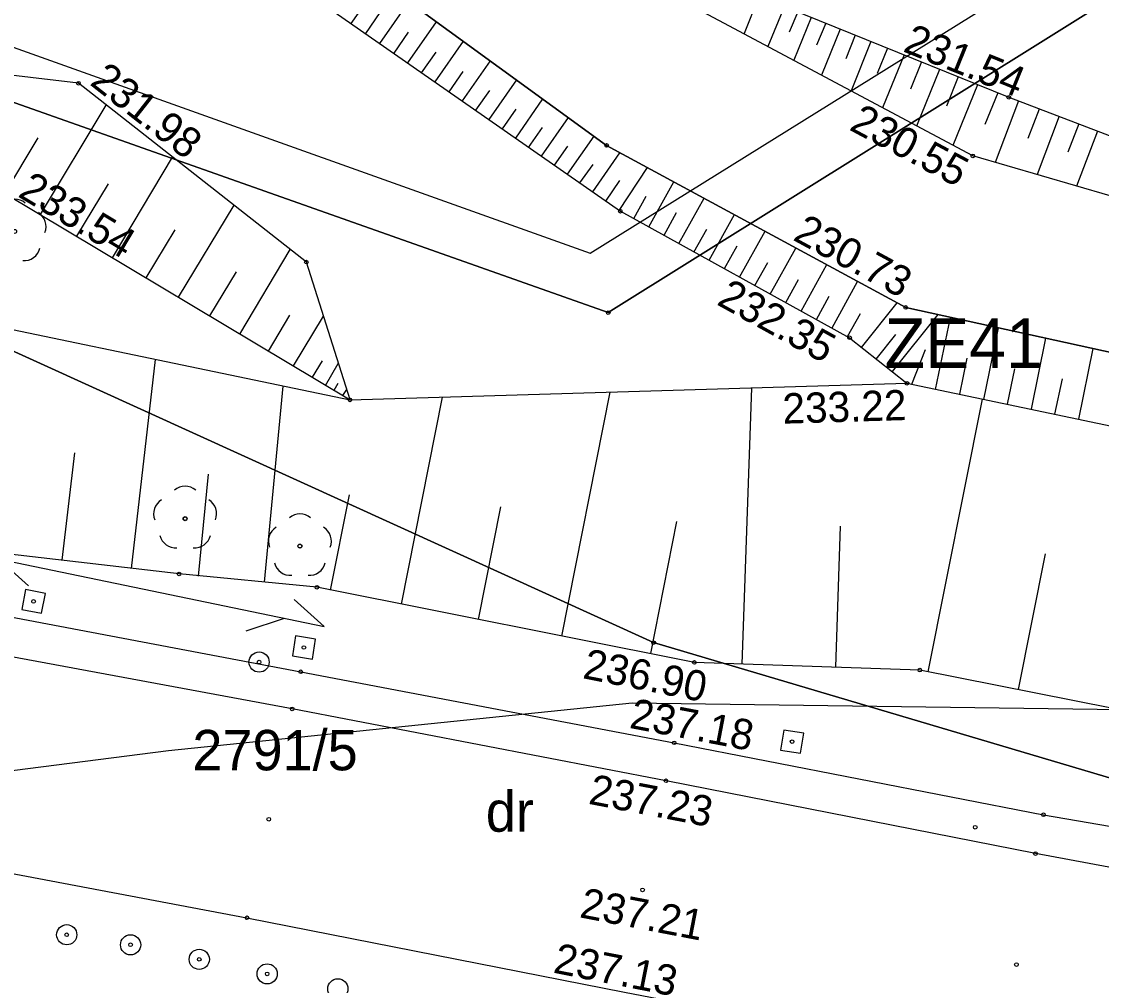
# Model space of a CAD drawing. Extents: x 6596400 to 6597200, y 5539751 to 5540251.
# Drawn here: x 6596761.51 to 6596788.23, y 5540079.28 to 5540103.13 of the extents above; entities that cross this region are included whole.
import ezdxf

# ---------------------------------------------------------------- set-up
doc = ezdxf.new("R2010")
doc.units = 0
for name, color, linetype in [('000 Inne (niezydentyfikowane)', 7, 'Continuous'), ('140-Punkty robocze', 7, 'Continuous'), ('203-punkt graniczny', 7, 'Continuous'), ('210-oznaczenie konturu użytku gruntowego', 7, 'Continuous'), ('211-numer działki ewidencyjnej', 7, 'Continuous'), ('217-kontur klasyfikacyjny', 7, 'Continuous'), ('218-kontur użytku gruntowego', 7, 'Continuous'), ('219-działka ewidencyjna', 7, 'Continuous'), ('bariera ochronna', 7, 'Continuous'), ('drzewo liściaste', 7, 'Continuous'), ('jezdnia', 7, 'Continuous'), ('Linia obszaru zagospodarowania terenu', 7, 'Continuous'), ('Opis obszaru zagospodarowania terenu', 7, 'Continuous'), ('pikieta sztuczna', 7, 'Continuous'), ('pikieta sztuczna-Atr2', 7, 'Continuous'), ('przewód telekomunikacyjny napowietrzny', 7, 'Continuous'), ('skarpa nieumocniona', 7, 'Continuous'), ('skarpa umocniona', 7, 'Continuous'), ('woda płynąca', 7, 'Continuous'), ('właz do komory lub kanału - kwadratowy', 7, 'Continuous'), ('właz do komory lub kanału - okrągły', 7, 'Continuous')]:
    doc.layers.add(name, color=color, linetype=linetype)

# ---------------------------------------------------------------- blocks, each defined once
blk = doc.blocks.new('203')
blk.add_circle((0, 0), 0.045)
blk = doc.blocks.new('SUTP')
for p, q in [((0, 0), (0.866, 0.5)), ((9.232, 0), (8.366, 0.5)), ((0, 0), (9.232, 0)), ((1.866, -0.5), (1, 0)), ((7.366, -0.5), (8.232, 0))]:
    blk.add_line(p, q)
blk = doc.blocks.new('OP021')
blk.add_circle((0, 0), 0.05)
for centre, start, end in [((0, 0.4), 49.272, 130.728), ((-0.38, 0.124), 121.308, 202.548), ((0.38, 0.124), 337.452, 58.692), ((-0.235, -0.324), 193.221, 274.871), ((0.235, -0.324), 265.129, 346.779)]:
    blk.add_arc(centre, 0.4, start, end)
blk = doc.blocks.new('US22A')
blk.add_lwpolyline([(-0.25, -0.25), (0.25, -0.25), (0.25, 0.25), (-0.25, 0.25)], close=True)
blk = doc.blocks.new('US22')
blk.add_circle((0, 0), 0.25)
blk = doc.blocks.new('PIKIETA')
blk.add_circle((0, 0), 0.045)
blk = doc.blocks.new('PW01')
blk.add_circle((0, 0), 0.045)

msp = doc.modelspace()

# ---------------------------------------------------------------- linework, layer by layer
at = {"layer": '000 Inne (niezydentyfikowane)'}
for p, q in [((6596779.76, 5540103.77), (6596779.39, 5540102.84)), ((6596780.39, 5540103.52), (6596779.98, 5540102.52)), ((6596780.72, 5540103.38), (6596780.51, 5540102.87)), ((6596781.05, 5540103.24), (6596780.62, 5540102.18)), ((6596781.41, 5540103.1), (6596781.18, 5540102.55)), ((6596781.77, 5540102.95), (6596781.31, 5540101.81)), ((6596782.14, 5540102.8), (6596781.91, 5540102.21)), ((6596782.53, 5540102.64), (6596782.04, 5540101.42)), ((6596782.94, 5540102.48), (6596782.68, 5540101.85)), ((6596783.35, 5540102.31), (6596782.82, 5540101)), ((6596783.78, 5540102.14), (6596783.51, 5540101.46)), ((6596784.23, 5540101.95), (6596783.66, 5540100.55)), ((6596784.69, 5540101.77), (6596784.4, 5540101.04)), ((6596785.17, 5540101.57), (6596784.56, 5540100.07)), ((6596785.67, 5540101.37), (6596785.35, 5540100.59)), ((6596786.18, 5540101.17), (6596785.6, 5540099.65)), ((6596786.69, 5540100.97), (6596786.41, 5540100.24)), ((6596787.19, 5540100.79), (6596786.64, 5540099.35)), ((6596787.67, 5540100.6), (6596787.4, 5540099.9)), ((6596788.14, 5540100.42), (6596787.62, 5540099.06)), ((6596764.23, 5540089.6), (6596764.83, 5540094.77)), ((6596767.52, 5540089.26), (6596767.99, 5540094.11)), ((6596774.88, 5540087.92), (6596776.08, 5540093.96)), ((6596779.34, 5540087.23), (6596779.58, 5540094.07)), ((6596770.91, 5540088.71), (6596771.93, 5540093.84)), ((6596783.95, 5540087.04), (6596785.29, 5540093.79)), ((6596762.52, 5540089.8), (6596762.83, 5540092.46)), ((6596765.89, 5540089.41), (6596766.14, 5540091.93)), ((6596769.16, 5540089.06), (6596769.63, 5540091.42)), ((6596772.82, 5540088.33), (6596773.37, 5540091.12)), ((6596777.08, 5540087.49), (6596777.73, 5540090.76)), ((6596781.66, 5540087.15), (6596781.78, 5540090.64)), ((6596786.18, 5540086.6), (6596786.85, 5540089.96))]:
    msp.add_line(p, q, dxfattribs=at)
for points in [[(6596769.67, 5540103.09), (6596770.41, 5540104.14)], [(6596770.38, 5540102.59), (6596771.1, 5540103.63)], [(6596770.03, 5540102.84), (6596770.39, 5540103.36)], [(6596771.07, 5540102.11), (6596771.78, 5540103.13)], [(6596770.73, 5540102.35), (6596771.09, 5540102.87)], [(6596771.75, 5540101.64), (6596772.45, 5540102.65)], [(6596771.41, 5540101.87), (6596771.77, 5540102.38)], [(6596772.42, 5540101.17), (6596773.12, 5540102.16)], [(6596772.09, 5540101.4), (6596772.44, 5540101.9)], [(6596773.08, 5540100.71), (6596773.77, 5540101.69)], [(6596772.75, 5540100.94), (6596773.1, 5540101.43)], [(6596773.74, 5540100.25), (6596774.41, 5540101.22)], [(6596761.98, 5540098.36), (6596763.61, 5540101.07)], [(6596773.41, 5540100.48), (6596773.75, 5540100.97)], [(6596774.38, 5540099.8), (6596775.05, 5540100.76)], [(6596774.06, 5540100.02), (6596774.4, 5540100.51)], [(6596761.1, 5540098.88), (6596761.92, 5540100.26)], [(6596774.7, 5540099.58), (6596775.03, 5540100.05)], [(6596775.02, 5540099.36), (6596775.68, 5540100.3)], [(6596763.76, 5540097.29), (6596765.25, 5540099.78)], [(6596775.65, 5540098.92), (6596776.32, 5540099.89)], [(6596775.33, 5540099.14), (6596775.66, 5540099.6)], [(6596776.3, 5540098.46), (6596777, 5540099.52)], [(6596762.88, 5540097.82), (6596763.66, 5540099.12)], [(6596775.97, 5540098.69), (6596776.32, 5540099.2)], [(6596777.03, 5540098.05), (6596777.65, 5540099.17)], [(6596776.66, 5540098.26), (6596776.97, 5540098.81)], [(6596777.78, 5540097.64), (6596778.4, 5540098.76)], [(6596765.4, 5540096.31), (6596766.77, 5540098.59)], [(6596777.41, 5540097.85), (6596777.72, 5540098.41)], [(6596778.53, 5540097.23), (6596779.15, 5540098.36)], [(6596764.6, 5540096.79), (6596765.31, 5540097.98)], [(6596778.15, 5540097.43), (6596778.47, 5540098)], [(6596779.28, 5540096.81), (6596779.91, 5540097.95)], [(6596766.91, 5540095.4), (6596768.16, 5540097.49)], [(6596778.91, 5540097.02), (6596779.22, 5540097.58)], [(6596780.04, 5540096.39), (6596780.67, 5540097.53)], [(6596779.66, 5540096.6), (6596779.98, 5540097.17)], [(6596780.8, 5540095.97), (6596781.44, 5540097.12)], [(6596766.17, 5540095.85), (6596766.83, 5540096.94)], [(6596780.42, 5540096.18), (6596780.74, 5540096.75)], [(6596781.57, 5540095.55), (6596782.2, 5540096.7)], [(6596781.18, 5540095.76), (6596781.5, 5540096.34)], [(6596782.3, 5540095.07), (6596783.18, 5540096.17)], [(6596767.62, 5540094.98), (6596768.15, 5540095.87)], [(6596768.24, 5540094.61), (6596768.98, 5540095.84)], [(6596781.95, 5540095.34), (6596782.27, 5540095.91)], [(6596783.06, 5540094.47), (6596784.19, 5540095.88)], [(6596784.13, 5540094.03), (6596784.5, 5540095.81)], [(6596785.32, 5540093.78), (6596785.69, 5540095.55)], [(6596782.66, 5540094.78), (6596783.15, 5540095.39)], [(6596786.5, 5540093.54), (6596786.86, 5540095.3)], [(6596783.54, 5540094.16), (6596783.88, 5540095.02)], [(6596787.67, 5540093.29), (6596788.03, 5540095.04)], [(6596768.71, 5540094.33), (6596768.96, 5540094.74)], [(6596784.73, 5540093.91), (6596784.91, 5540094.8)], [(6596769.03, 5540094.13), (6596769.35, 5540094.67)], [(6596785.91, 5540093.66), (6596786.09, 5540094.54)], [(6596769.25, 5540094.01), (6596769.35, 5540094.18)], [(6596787.08, 5540093.42), (6596787.27, 5540094.29)], [(6596769.46, 5540093.88), (6596769.56, 5540094.03)]]:
    msp.add_lwpolyline(points, dxfattribs=at)
at = {"layer": '217-kontur klasyfikacyjny'}
for points in [[(6596791.43, 5540105.56), (6596776.03, 5540095.93)], [(6596776.03, 5540095.93), (6596757.93, 5540102.33)], [(6596758.2, 5540096.39), (6596777.15, 5540087.76)], [(6596777.15, 5540087.76), (6596798.41, 5540081.45)]]:
    msp.add_lwpolyline(points, dxfattribs=at)
at = {"layer": '218-kontur użytku gruntowego'}
for points in [[(6596776.03, 5540095.93), (6596791.43, 5540105.56)], [(6596791.43, 5540105.56), (6596776.03, 5540095.93)], [(6596757.93, 5540102.33), (6596776.03, 5540095.93)], [(6596776.03, 5540095.93), (6596757.93, 5540102.33)], [(6596758.2, 5540096.39), (6596777.15, 5540087.76)], [(6596777.15, 5540087.76), (6596758.2, 5540096.39)], [(6596777.15, 5540087.76), (6596798.41, 5540081.45)], [(6596798.41, 5540081.45), (6596777.15, 5540087.76)]]:
    msp.add_lwpolyline(points, dxfattribs=at)
at = {"layer": '219-działka ewidencyjna'}
for points in [[(6596776.03, 5540095.93), (6596791.43, 5540105.56)], [(6596776.03, 5540095.93), (6596757.93, 5540102.33)], [(6596758.2, 5540096.39), (6596777.15, 5540087.76)], [(6596798.41, 5540081.45), (6596777.15, 5540087.76)]]:
    msp.add_lwpolyline(points, dxfattribs=at)
at = {"layer": 'bariera ochronna'}
msp.add_lwpolyline([(6596724.82, 5540100.27), (6596724.21, 5540095.84), (6596728.33, 5540094.88), (6596750, 5540090.55), (6596759.32, 5540088.76), (6596768.42, 5540087.04), (6596777.66, 5540085.28), (6596786.8, 5540083.5), (6596789.01, 5540083.12), (6596792.87, 5540082.26), (6596795.36, 5540081.78), (6596800.78, 5540080.9), (6596809.14, 5540079.91)], dxfattribs=at)
at = {"layer": 'jezdnia'}
for points in [[(6596828.719, 5540062.578), (6596825.42, 5540065.32), (6596821.78, 5540067.97), (6596818.46, 5540070.24), (6596813.26, 5540073.35), (6596810.44, 5540074.77), (6596805.94, 5540076.86), (6596804.14, 5540077.61), (6596801.52, 5540078.62), (6596798.28, 5540079.76), (6596795.16, 5540080.71), (6596792.67, 5540081.35), (6596788.77, 5540082.14), (6596786.6, 5540082.54), (6596777.46, 5540084.34), (6596768.21, 5540086.12), (6596759.17, 5540087.8), (6596749.8, 5540089.83), (6596749.82, 5540090.44), (6596743.18, 5540091.67), (6596739.76, 5540092.34), (6596735.83, 5540093.08), (6596728.26, 5540094.5), (6596723.35, 5540095.14)], [(6596748.72, 5540084.9), (6596758.31, 5540082.61), (6596767.09, 5540080.95), (6596776.43, 5540079.11), (6596785.57, 5540077.35), (6596790.64, 5540076.33), (6596793.76, 5540075.4), (6596796, 5540074.75), (6596799.11, 5540073.89), (6596802.37, 5540072.55), (6596804.34, 5540071.72), (6596806.42, 5540070.73), (6596808.2, 5540069.72), (6596810.28, 5540068.61), (6596812.76, 5540067.19), (6596815.5, 5540065.85), (6596818.95, 5540063.45), (6596822.11, 5540061.14), (6596825.559, 5540058.298)]]:
    msp.add_lwpolyline(points, dxfattribs=at)
at = {"layer": 'Linia obszaru zagospodarowania terenu'}
for points in [[(6596664.616, 5540132.112), (6596671.21, 5540127.95), (6596681.8, 5540121.54), (6596690.35, 5540115.69), (6596701.61, 5540105.97), (6596709.34, 5540098.61), (6596715.39, 5540091.82), (6596718.63, 5540088.53), (6596721.87, 5540084.71), (6596726.1, 5540083.21), (6596730.7, 5540082.79), (6596730.91, 5540075), (6596745.51, 5540074.64), (6596746.77, 5540082.74), (6596765.15, 5540085.09), (6596776.62, 5540086.27), (6596789.34, 5540086.1), (6596798.37, 5540085.54), (6596805.65, 5540083.56), (6596813.11, 5540081.53), (6596819.41, 5540077.54), (6596826.58, 5540072.81), (6596832.721, 5540067.998)], [(6596746.77, 5540082.74), (6596749.37, 5540097.92), (6596757.81, 5540103.76), (6596775.58, 5540097.4), (6596790.99, 5540107), (6596791.128, 5540108.731)]]:
    msp.add_lwpolyline(points, dxfattribs=at)
at = {"layer": 'skarpa nieumocniona'}
for points in [[(6596736.14, 5540074.83), (6596735.19, 5540080.23), (6596735.33, 5540085.41), (6596734.65, 5540089.1), (6596735.44, 5540093.45), (6596735.8, 5540095.62), (6596737, 5540098.15), (6596738.35, 5540109.49), (6596736.12, 5540109.87), (6596735.6, 5540111.55), (6596739.06, 5540111.12), (6596739.7, 5540112.38), (6596741.35, 5540114.97), (6596743.9, 5540116.21), (6596748.71, 5540116.3), (6596760.37, 5540114.69), (6596767.09, 5540112.87), (6596773.08, 5540108.54), (6596778.11, 5540104.44), (6596785.94, 5540101.26), (6596790.69, 5540099.45)], [(6596736.14, 5540074.83), (6596735.19, 5540080.23), (6596735.33, 5540085.41), (6596734.65, 5540089.1), (6596735.44, 5540093.45), (6596735.8, 5540095.62), (6596737, 5540098.15), (6596738.35, 5540109.49), (6596736.12, 5540109.87), (6596735.6, 5540111.55), (6596739.06, 5540111.12), (6596739.7, 5540112.38), (6596741.35, 5540114.97), (6596743.9, 5540116.21), (6596748.71, 5540116.3), (6596760.37, 5540114.69), (6596767.09, 5540112.87), (6596773.08, 5540108.54), (6596778.11, 5540104.44), (6596785.94, 5540101.26), (6596790.69, 5540099.45)], [(6596790.15, 5540098.33), (6596785.05, 5540099.81), (6596777.76, 5540103.71), (6596772.25, 5540107.73), (6596766.79, 5540112.11), (6596760.34, 5540113.97), (6596748.88, 5540115.79), (6596744.15, 5540115.57), (6596742.04, 5540114.13), (6596740.39, 5540112.04), (6596739.35, 5540110.21), (6596737.64, 5540097.87), (6596736.29, 5540093.37), (6596736.04, 5540089.3), (6596736.53, 5540085.88), (6596736.56, 5540080.1), (6596736.48, 5540078.77)], [(6596790.15, 5540098.33), (6596785.05, 5540099.81), (6596777.76, 5540103.71), (6596772.25, 5540107.73), (6596766.79, 5540112.11), (6596760.34, 5540113.97), (6596748.88, 5540115.79), (6596744.15, 5540115.57), (6596742.04, 5540114.13), (6596740.39, 5540112.04), (6596739.35, 5540110.21), (6596737.64, 5540097.87), (6596736.29, 5540093.37), (6596736.04, 5540089.3), (6596736.53, 5540085.88), (6596736.56, 5540080.1), (6596736.48, 5540078.77)], [(6596792.35, 5540085.37), (6596783.74, 5540087.08), (6596778.16, 5540087.27), (6596768.82, 5540089.13), (6596765.41, 5540089.46), (6596759.5, 5540090.15), (6596751.76, 5540092.75), (6596750.9, 5540093.05), (6596752.08, 5540098.31), (6596752.65, 5540098.36), (6596757.12, 5540096.38), (6596769.64, 5540093.77), (6596783.42, 5540094.18), (6596788.65, 5540093.09)], [(6596792.35, 5540085.37), (6596783.74, 5540087.08), (6596778.16, 5540087.27), (6596768.82, 5540089.13), (6596765.41, 5540089.46), (6596759.5, 5540090.15), (6596751.76, 5540092.75), (6596750.9, 5540093.05), (6596752.08, 5540098.31), (6596752.65, 5540098.36), (6596757.12, 5540096.38), (6596769.64, 5540093.77), (6596783.42, 5540094.18), (6596788.65, 5540093.09)]]:
    msp.add_lwpolyline(points, dxfattribs=at)
msp.add_lwpolyline([(6596769.64, 5540093.77), (6596768.56, 5540097.18), (6596762.92, 5540101.61), (6596753.55, 5540102.72), (6596755.23, 5540100.63), (6596761.09, 5540098.89)], close=True, dxfattribs=at)
msp.add_lwpolyline([(6596769.64, 5540093.77), (6596768.56, 5540097.18), (6596762.92, 5540101.61), (6596753.55, 5540102.72), (6596755.23, 5540100.63), (6596761.09, 5540098.89)], close=True, dxfattribs=at)
at = {"layer": 'skarpa umocniona'}
msp.add_lwpolyline([(6596768.41, 5540103.97), (6596776.33, 5540098.44), (6596782, 5540095.31), (6596783.42, 5540094.18), (6596788.65, 5540093.09), (6596792.84, 5540092.11), (6596803.9, 5540094.29), (6596790.43, 5540094.51), (6596783.39, 5540096.06), (6596775.99, 5540100.07), (6596769.44, 5540104.84)], close=True, dxfattribs=at)
msp.add_lwpolyline([(6596768.41, 5540103.97), (6596776.33, 5540098.44), (6596782, 5540095.31), (6596783.42, 5540094.18), (6596788.65, 5540093.09), (6596792.84, 5540092.11), (6596803.9, 5540094.29), (6596790.43, 5540094.51), (6596783.39, 5540096.06), (6596775.99, 5540100.07), (6596769.44, 5540104.84)], close=True, dxfattribs=at)
at = {"layer": 'woda płynąca'}
for points in [[(6596801.146, 5540105.126), (6596800.55, 5540103.15), (6596798.59, 5540101.49), (6596797.54, 5540099.56), (6596796.12, 5540099.28), (6596790.15, 5540098.33), (6596785.05, 5540099.81), (6596777.76, 5540103.71), (6596772.25, 5540107.73), (6596766.79, 5540112.11), (6596760.34, 5540113.97), (6596748.88, 5540115.79), (6596744.15, 5540115.57), (6596742.04, 5540114.13), (6596740.39, 5540112.04), (6596739.35, 5540110.21), (6596737.64, 5540097.87), (6596736.29, 5540093.37), (6596736.04, 5540089.3), (6596736.53, 5540085.88)], [(6596746.88, 5540042.02), (6596743.2, 5540046.89), (6596742.01, 5540050.53), (6596741.65, 5540054.82), (6596742.47, 5540061.97), (6596743.25, 5540066.3), (6596741.68, 5540074.92), (6596740.68, 5540078.45), (6596740.72, 5540079.85), (6596740.91, 5540084.82), (6596741.25, 5540084.94), (6596740.92, 5540088.42), (6596742.42, 5540096.36), (6596743.6, 5540103.66), (6596744.49, 5540107.55), (6596747.66, 5540110.25), (6596750.9, 5540111.08), (6596759.95, 5540110.31), (6596765.11, 5540108.34), (6596769.44, 5540104.84), (6596775.99, 5540100.07), (6596783.39, 5540096.06), (6596790.43, 5540094.51)]]:
    msp.add_lwpolyline(points, dxfattribs=at)

# ---------------------------------------------------------------- block references
at = {"layer": '140-Punkty robocze'}
for p in [(6596762.92, 5540101.61), (6596775.99, 5540100.07), (6596785.05, 5540099.81), (6596776.33, 5540098.44), (6596768.56, 5540097.18), (6596783.39, 5540096.06), (6596782, 5540095.31), (6596783.42, 5540094.18), (6596769.64, 5540093.77), (6596765.56, 5540090.83), (6596768.4, 5540090.15), (6596765.41, 5540089.46), (6596768.82, 5540089.13), (6596761.81, 5540088.78), (6596768.5, 5540087.64), (6596767.39, 5540087.28), (6596768.42, 5540087.04), (6596783.74, 5540087.08), (6596768.21, 5540086.12), (6596780.58, 5540085.31), (6596786.8, 5540083.5), (6596767.63, 5540083.39), (6596785.11, 5540083.19), (6596786.6, 5540082.54), (6596767.09, 5540080.95), (6596762.63, 5540080.53), (6596764.21, 5540080.28), (6596765.91, 5540079.92), (6596786.13, 5540079.79), (6596767.59, 5540079.56)]:
    msp.add_blockref('PIKIETA', p, dxfattribs=at)
at = {"layer": '203-punkt graniczny'}
for p in [(6596776.03, 5540095.93), (6596777.15, 5540087.76)]:
    msp.add_blockref('203', p, dxfattribs=at)
at = {"layer": 'drzewo liściaste'}
for p in [(6596761.34, 5540097.94), (6596765.56, 5540090.83), (6596768.4, 5540090.15)]:
    msp.add_blockref('OP021', p, dxfattribs=at)
at = {"layer": 'pikieta sztuczna'}
for p in [(6596762.92, 5540101.61), (6596785.94, 5540101.26), (6596785.05, 5540099.81), (6596783.39, 5540096.06), (6596782, 5540095.31), (6596783.42, 5540094.18), (6596778.16, 5540087.27), (6596777.66, 5540085.28), (6596777.46, 5540084.34), (6596776.88, 5540081.64)]:
    msp.add_blockref('PW01', p, dxfattribs=at)
at = {"layer": 'przewód telekomunikacyjny napowietrzny', "rotation": -11.666000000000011}
msp.add_blockref('SUTP', (6596759.96, 5540090.03), dxfattribs=at)
at = {"layer": 'właz do komory lub kanału - kwadratowy'}
for p, rotation in [((6596761.81, 5540088.78), -10.886000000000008), ((6596768.5, 5540087.64), -8.97300000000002), ((6596780.58, 5540085.31), -9.039000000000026)]:
    msp.add_blockref('US22A', p, dxfattribs=dict(at, rotation=rotation))
at = {"layer": 'właz do komory lub kanału - okrągły'}
for p in [(6596767.39, 5540087.28), (6596762.63, 5540080.53), (6596764.21, 5540080.28), (6596765.91, 5540079.92), (6596767.59, 5540079.56), (6596769.34, 5540079.19)]:
    msp.add_blockref('US22', p, dxfattribs=at)

# ---------------------------------------------------------------- texts
at = {"layer": '210-oznaczenie konturu użytku gruntowego'}
msp.add_text('dr', height=1, dxfattribs=at).set_placement((6596773, 5540083.08))
at = {"layer": '211-numer działki ewidencyjnej'}
msp.add_text('2791/5', height=1, dxfattribs=at).set_placement((6596765.74, 5540084.6))
at = {"layer": 'Opis obszaru zagospodarowania terenu'}
msp.add_text('ZE41', height=1.225, dxfattribs=at).set_placement((6596782.87, 5540094.56))
at = {"layer": 'pikieta sztuczna-Atr2'}
for s, rotation, p in [('231.54', 337.896, (6596783.298, 5540102.405)), ('231.98', 321.852, (6596763.177, 5540101.59)), ('230.55', 331.854, (6596781.966, 5540100.469)), ('233.54', 329.086, (6596761.395, 5540098.817)), ('230.73', 331.547, (6596780.573, 5540097.741)), ('232.35', 331.1, (6596778.688, 5540096.143)), ('233.22', 1.704, (6596780.352, 5540093.18)), ('236.90', 348.737, (6596775.374, 5540086.884)), ('237.18', 349.216, (6596776.53, 5540085.653)), ('237.23', 349.108, (6596775.518, 5540083.774)), ('237.21', 349.108, (6596775.298, 5540080.964)), ('237.13', 348.855, (6596774.645, 5540079.594))]:
    msp.add_text(s, height=0.75, rotation=rotation, dxfattribs=at).set_placement(p)

doc.saveas('drawing.dxf')
